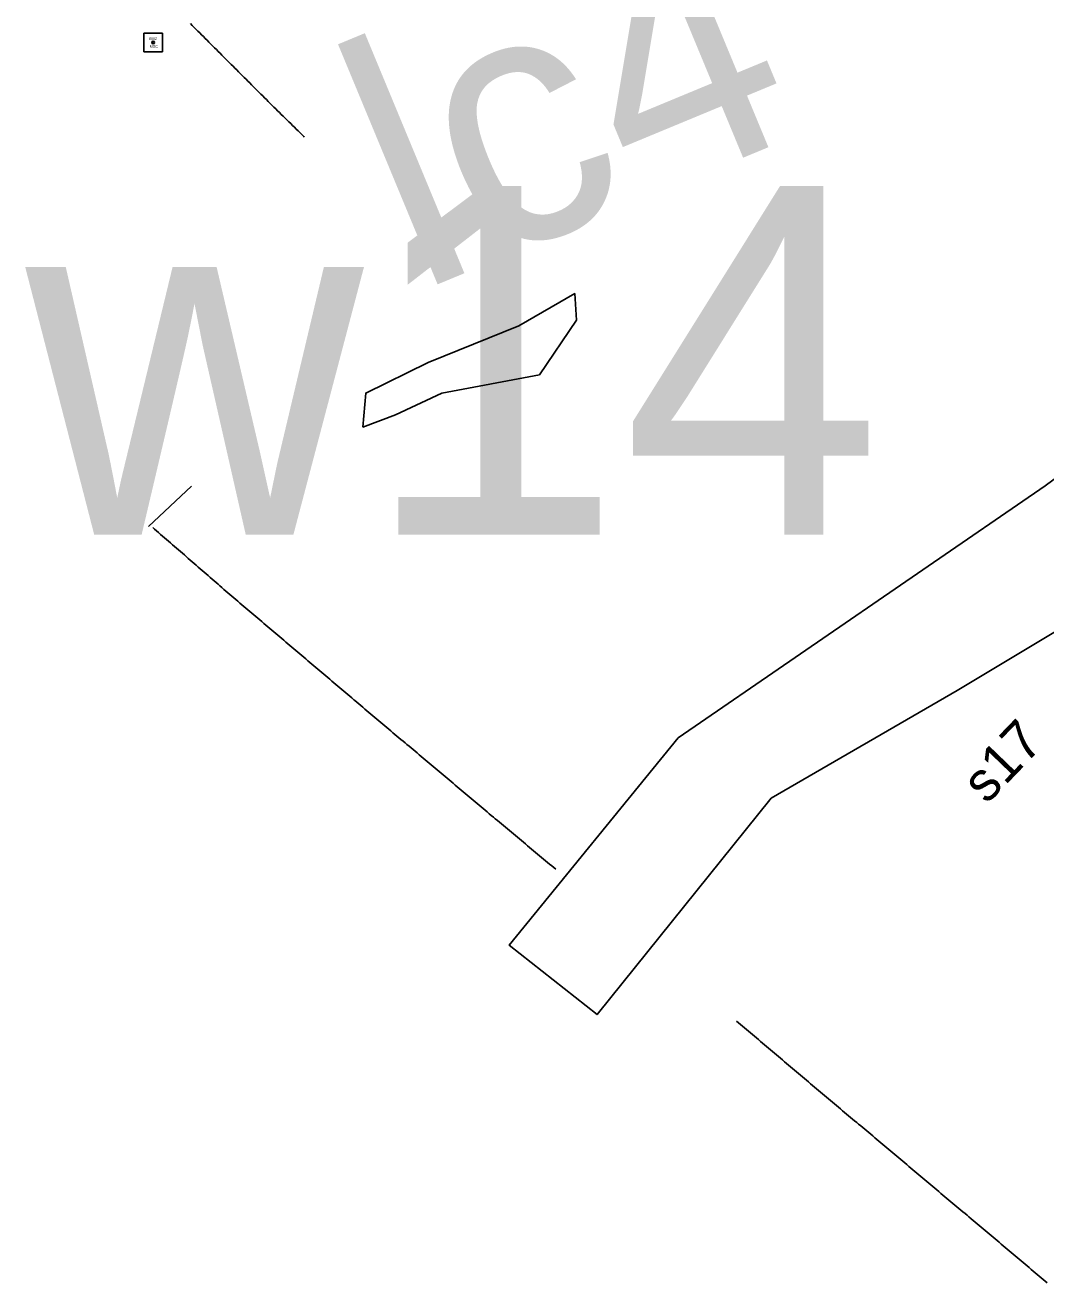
# Model space of a CAD drawing. Extents: x 205929 to 2357175, y -1785700 to 846739.
# Drawn here: x 2015000.6 to 2015389.7, y 820120.8 to 820600.5 of the extents above; entities that cross this region are included whole.
import ezdxf

# ---------------------------------------------------------------- set-up
doc = ezdxf.new("R2010")
doc.units = 0
for name, color, linetype in [('Default', 7, 'Continuous'), ('RD_EV_JTrib', 7, 'Continuous'), ('RD_EV_JW', 7, 'Continuous'), ('RD_EV_TX', 7, 'Continuous'), ('RD_HC_Survey', 7, 'Continuous'), ('RD_HC_txCode', 7, 'Continuous'), ('RD_Sketch1', 7, 'Continuous'), ('RD_SMD_Locator', 7, 'Continuous')]:
    doc.layers.add(name, color=color, linetype=linetype)

# ---------------------------------------------------------------- blocks, each defined once
blk = doc.blocks.new('POL00035')
at = {"layer": 'Default'}
blk.add_lwpolyline([(-11.11, -6.11), (-10.83, -2.82), (-4.79, 0.15), (4, 3.68), (9.41, 6.81), (9.59, 4.24), (5.99, -1.07), (-3.47, -2.84), (-7.94, -4.92)], close=True, dxfattribs=at)
blk = doc.blocks.new('POL0004A')
at = {"layer": 'Default'}
blk.add_lwpolyline([(60.33, 13.59), (59.28, 8.76), (45.95, 7.51), (36.02, 6.26), (27.95, 7.47), (13.76, 1.34), (-7.33, -11.33), (-25.33, -21.78), (-42.2, -42.73), (-50.71, -36.02), (-34.36, -15.93), (1.19, 8.51), (18.3, 21.11), (10.42, 34.97), (6.36, 42.61), (11.85, 51.93), (21.89, 20.87), (27.16, 12.26), (33.82, 12.71), (47.53, 14.82)], close=True, dxfattribs=at)

msp = doc.modelspace()

# ---------------------------------------------------------------- linework, layer by layer
at = {"layer": 'RD_HC_Survey'}
msp.add_lwpolyline([(2015052.92, 820597.45), (2015045.85, 820597.45), (2015045.85, 820590.38), (2015052.92, 820590.38)], close=True, dxfattribs=at)
msp.add_circle((2015049.38, 820593.91), 0.5, dxfattribs=at)
at = {"layer": 'RD_Sketch1'}
for points in [[(2015063.58, 820601.1), (2015064.29, 820600.39), (2015065, 820599.68), (2015065.7, 820598.98), (2015066.41, 820598.27), (2015067.11, 820597.56), (2015067.82, 820596.85), (2015068.53, 820596.14), (2015069.23, 820595.44), (2015069.94, 820594.73), (2015070.65, 820594.02), (2015071.36, 820593.32), (2015072.06, 820592.61), (2015072.77, 820591.9), (2015073.48, 820591.19), (2015074.18, 820590.49), (2015074.89, 820589.78), (2015075.6, 820589.07), (2015076.3, 820588.36), (2015077.01, 820587.66), (2015077.72, 820586.95), (2015078.42, 820586.24), (2015079.13, 820585.54), (2015079.84, 820584.83), (2015080.54, 820584.12), (2015081.25, 820583.41), (2015081.96, 820582.71), (2015082.67, 820582), (2015083.37, 820581.29), (2015084.08, 820580.58), (2015084.79, 820579.88), (2015085.49, 820579.17), (2015086.2, 820578.46), (2015086.91, 820577.76), (2015087.61, 820577.05), (2015088.32, 820576.34), (2015089.03, 820575.63), (2015089.73, 820574.93), (2015090.44, 820574.22), (2015091.15, 820573.51), (2015091.86, 820572.8), (2015092.56, 820572.1), (2015093.27, 820571.39), (2015093.98, 820570.68), (2015094.68, 820569.98), (2015095.39, 820569.27), (2015096.11, 820568.57), (2015096.82, 820567.87), (2015097.53, 820567.17), (2015098.24, 820566.46), (2015098.96, 820565.76), (2015099.67, 820565.06), (2015100.38, 820564.36), (2015101.09, 820563.66), (2015101.81, 820562.96), (2015102.52, 820562.25), (2015103.23, 820561.55), (2015103.94, 820560.85), (2015104.66, 820560.15), (2015105.37, 820559.45), (2015106.08, 820558.75), (2015106.79, 820558.05), (2015107, 820557.84)], [(2015063.95, 820424.68), (2015047.61, 820409.24)], [(2015049.19, 820408.91), (2015049.95, 820408.25), (2015050.7, 820407.6), (2015051.46, 820406.94), (2015052.21, 820406.29), (2015052.97, 820405.63), (2015053.72, 820404.97), (2015054.48, 820404.32), (2015055.23, 820403.66), (2015055.99, 820403.01), (2015056.74, 820402.35), (2015057.5, 820401.7), (2015058.25, 820401.04), (2015059.01, 820400.39), (2015059.76, 820399.73), (2015060.52, 820399.07), (2015061.27, 820398.42), (2015062.03, 820397.76), (2015062.78, 820397.11), (2015063.54, 820396.45), (2015064.29, 820395.8), (2015065.05, 820395.14), (2015065.8, 820394.49), (2015066.56, 820393.83), (2015067.31, 820393.18), (2015068.07, 820392.52), (2015068.82, 820391.86), (2015069.58, 820391.21), (2015070.33, 820390.55), (2015071.09, 820389.9), (2015071.84, 820389.24), (2015072.6, 820388.59), (2015073.35, 820387.93), (2015074.11, 820387.28), (2015074.86, 820386.62), (2015075.61, 820385.96), (2015076.37, 820385.31), (2015077.12, 820384.65), (2015077.88, 820384), (2015078.64, 820383.35), (2015079.4, 820382.7), (2015080.17, 820382.06), (2015080.93, 820381.41), (2015081.69, 820380.76), (2015082.45, 820380.11), (2015083.22, 820379.47), (2015083.98, 820378.82), (2015084.74, 820378.17), (2015085.5, 820377.53), (2015086.26, 820376.88), (2015087.03, 820376.23), (2015087.79, 820375.59), (2015088.55, 820374.94), (2015089.31, 820374.29), (2015090.07, 820373.64), (2015090.84, 820373), (2015091.6, 820372.35), (2015092.36, 820371.7), (2015093.12, 820371.06), (2015093.89, 820370.41), (2015094.65, 820369.76), (2015095.41, 820369.11), (2015096.17, 820368.47), (2015096.93, 820367.82), (2015097.7, 820367.17), (2015097.7, 820367.17), (2015098.46, 820366.53), (2015099.22, 820365.88), (2015099.98, 820365.23), (2015100.75, 820364.58), (2015101.51, 820363.94), (2015102.27, 820363.29), (2015103.03, 820362.64), (2015103.79, 820362), (2015104.56, 820361.35), (2015105.32, 820360.7), (2015106.08, 820360.05), (2015106.84, 820359.41), (2015107.61, 820358.76), (2015108.37, 820358.11), (2015109.13, 820357.47), (2015109.89, 820356.82), (2015110.65, 820356.17), (2015111.42, 820355.52), (2015112.18, 820354.88), (2015112.94, 820354.23), (2015113.7, 820353.58), (2015114.46, 820352.94), (2015115.23, 820352.29), (2015115.99, 820351.64), (2015116.75, 820351), (2015117.51, 820350.35), (2015118.28, 820349.7), (2015119.04, 820349.05), (2015119.8, 820348.41), (2015120.56, 820347.76), (2015121.32, 820347.11), (2015122.09, 820346.47), (2015122.85, 820345.82), (2015123.61, 820345.17), (2015124.37, 820344.53), (2015125.13, 820343.88), (2015125.9, 820343.23), (2015126.29, 820342.9), (2015127.06, 820342.25), (2015127.82, 820341.61), (2015128.59, 820340.96), (2015129.35, 820340.32), (2015130.11, 820339.67), (2015130.88, 820339.03), (2015131.64, 820338.38), (2015132.41, 820337.74), (2015133.17, 820337.09), (2015133.94, 820336.45), (2015134.7, 820335.8), (2015135.46, 820335.16), (2015136.23, 820334.52), (2015136.99, 820333.87), (2015137.76, 820333.23), (2015138.52, 820332.58), (2015139.29, 820331.94), (2015140.05, 820331.29), (2015140.81, 820330.65), (2015141.58, 820330), (2015142.34, 820329.36), (2015143.11, 820328.71), (2015143.87, 820328.07), (2015144.64, 820327.42), (2015145.4, 820326.78), (2015146.16, 820326.13), (2015146.93, 820325.49), (2015147.69, 820324.84), (2015148.46, 820324.2), (2015149.22, 820323.55), (2015149.99, 820322.91), (2015150.75, 820322.26), (2015151.51, 820321.62), (2015152.28, 820320.97), (2015153.04, 820320.33), (2015153.81, 820319.69), (2015154.58, 820319.05), (2015155.34, 820318.4), (2015156.11, 820317.76), (2015156.87, 820317.12), (2015157.64, 820316.47), (2015158.4, 820315.83), (2015159.17, 820315.19), (2015159.94, 820314.54), (2015160.7, 820313.9), (2015161.47, 820313.26), (2015162.23, 820312.62), (2015163, 820311.97), (2015163.76, 820311.33), (2015164.53, 820310.69), (2015165.3, 820310.04), (2015166.06, 820309.4), (2015166.83, 820308.76), (2015167.59, 820308.11), (2015168.36, 820307.47), (2015169.12, 820306.83), (2015169.89, 820306.18), (2015170.66, 820305.54), (2015171.42, 820304.9), (2015172.19, 820304.26), (2015172.95, 820303.61), (2015173.72, 820302.97), (2015174.48, 820302.33), (2015175.25, 820301.68), (2015175.25, 820301.68), (2015176.02, 820301.04), (2015176.78, 820300.4), (2015177.55, 820299.75), (2015178.31, 820299.11), (2015179.08, 820298.47), (2015179.84, 820297.83), (2015180.61, 820297.18), (2015181.38, 820296.54), (2015182.14, 820295.9), (2015182.91, 820295.25), (2015183.67, 820294.61), (2015184.44, 820293.97), (2015185.2, 820293.32), (2015185.97, 820292.68), (2015186.74, 820292.04), (2015187.5, 820291.4), (2015188.27, 820290.76), (2015189.04, 820290.12), (2015189.81, 820289.48), (2015190.57, 820288.83), (2015191.34, 820288.19), (2015192.11, 820287.55), (2015192.88, 820286.91), (2015193.64, 820286.27), (2015194.41, 820285.63), (2015195.18, 820284.99), (2015195.95, 820284.35), (2015196.71, 820283.71), (2015197.48, 820283.06), (2015198.25, 820282.42), (2015199.02, 820281.78), (2015199.78, 820281.14), (2015200.55, 820280.5), (2015201.32, 820279.86), (2015202.09, 820279.22), (2015202.85, 820278.58), (2015202.92, 820278.53)], [(2015271.76, 820220.66), (2015272.52, 820220.02), (2015273.29, 820219.37), (2015274.05, 820218.72), (2015274.81, 820218.08), (2015275.58, 820217.43), (2015276.34, 820216.79), (2015277.1, 820216.14), (2015277.87, 820215.49), (2015278.63, 820214.85), (2015279.39, 820214.2), (2015280.16, 820213.56), (2015280.92, 820212.91), (2015281.68, 820212.27), (2015282.45, 820211.62), (2015283.21, 820210.97), (2015283.97, 820210.33), (2015284.74, 820209.68), (2015285.5, 820209.04), (2015286.26, 820208.39), (2015287.03, 820207.74), (2015287.79, 820207.1), (2015288.55, 820206.45), (2015289.32, 820205.81), (2015290.08, 820205.16), (2015290.84, 820204.51), (2015291.61, 820203.87), (2015292.37, 820203.22), (2015293.13, 820202.58), (2015293.9, 820201.93), (2015294.66, 820201.29), (2015295.42, 820200.64), (2015296.19, 820199.99), (2015296.95, 820199.35), (2015297.71, 820198.7), (2015298.48, 820198.06), (2015299.24, 820197.41), (2015300, 820196.76), (2015300.77, 820196.12), (2015301.53, 820195.47), (2015302.3, 820194.83), (2015303.06, 820194.19), (2015303.83, 820193.54), (2015304.59, 820192.9), (2015305.36, 820192.26), (2015306.12, 820191.61), (2015306.89, 820190.97), (2015307.66, 820190.33), (2015308.42, 820189.68), (2015309.19, 820189.04), (2015309.95, 820188.4), (2015310.72, 820187.75), (2015311.48, 820187.11), (2015312.25, 820186.47), (2015313.01, 820185.82), (2015313.78, 820185.18), (2015314.54, 820184.54), (2015315.31, 820183.89), (2015316.08, 820183.25), (2015316.84, 820182.61), (2015317.61, 820181.96), (2015318.37, 820181.32), (2015319.14, 820180.68), (2015319.9, 820180.03), (2015320.67, 820179.39), (2015320.67, 820179.39), (2015321.43, 820178.75), (2015322.2, 820178.1), (2015322.96, 820177.46), (2015323.73, 820176.82), (2015324.5, 820176.17), (2015325.26, 820175.53), (2015326.03, 820174.89), (2015326.79, 820174.24), (2015327.56, 820173.6), (2015328.32, 820172.96), (2015329.09, 820172.31), (2015329.85, 820171.67), (2015330.62, 820171.03), (2015331.38, 820170.38), (2015332.15, 820169.74), (2015332.92, 820169.1), (2015333.68, 820168.45), (2015334.45, 820167.81), (2015335.21, 820167.17), (2015335.97, 820166.52), (2015336.74, 820165.88), (2015337.5, 820165.23), (2015338.27, 820164.59), (2015339.03, 820163.95), (2015339.8, 820163.3), (2015340.56, 820162.66), (2015341.33, 820162.01), (2015342.09, 820161.37), (2015342.86, 820160.73), (2015343.62, 820160.08), (2015344.39, 820159.44), (2015345.15, 820158.8), (2015345.92, 820158.15), (2015346.68, 820157.51), (2015347.45, 820156.86), (2015348.21, 820156.22), (2015348.97, 820155.58), (2015349.74, 820154.93), (2015350.5, 820154.29), (2015351.27, 820153.64), (2015352.03, 820153), (2015352.8, 820152.36), (2015353.56, 820151.71), (2015354.33, 820151.07), (2015355.09, 820150.43), (2015355.86, 820149.78), (2015356.62, 820149.14), (2015357.39, 820148.49), (2015358.15, 820147.85), (2015358.92, 820147.21), (2015359.68, 820146.56), (2015360.44, 820145.92), (2015361.21, 820145.27), (2015361.97, 820144.63), (2015362.74, 820143.99), (2015363.5, 820143.34), (2015364.27, 820142.7), (2015365.03, 820142.05), (2015365.8, 820141.41), (2015366.56, 820140.77), (2015367.33, 820140.12), (2015368.09, 820139.48), (2015368.86, 820138.83), (2015369.62, 820138.19), (2015369.62, 820138.19), (2015370.38, 820137.55), (2015371.15, 820136.9), (2015371.91, 820136.26), (2015372.68, 820135.61), (2015373.44, 820134.97), (2015374.21, 820134.33), (2015374.97, 820133.68), (2015375.74, 820133.04), (2015376.5, 820132.39), (2015377.27, 820131.75), (2015378.03, 820131.11), (2015378.79, 820130.46), (2015379.56, 820129.82), (2015380.32, 820129.17), (2015381.09, 820128.53), (2015381.85, 820127.89), (2015382.62, 820127.24), (2015383.38, 820126.6), (2015384.15, 820125.95), (2015384.91, 820125.31), (2015385.68, 820124.67), (2015386.44, 820124.02), (2015387.2, 820123.38), (2015387.97, 820122.73), (2015388.73, 820122.09), (2015389.5, 820121.45), (2015390.26, 820120.8)]]:
    msp.add_lwpolyline(points, dxfattribs=at)
at = {"layer": 'RD_SMD_Locator'}
msp.add_circle((2015049.38, 820593.91), 0.001, dxfattribs=at)

# ---------------------------------------------------------------- block references
at = {"layer": 'RD_EV_JTrib', "xscale": 3.937007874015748, "yscale": 3.937007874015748}
msp.add_blockref('POL0004A', (2015384.79, 820391.36), dxfattribs=at)
at = {"layer": 'RD_EV_JW', "xscale": 3.937007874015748, "yscale": 3.937007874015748}
msp.add_blockref('POL00035', (2015173.06, 820471.29), dxfattribs=at)

# ---------------------------------------------------------------- texts
at = {"layer": 'RD_EV_TX'}
for s, height, rotation, p in [('lc4', 94.115, 22.5227, (2015150, 820498.4)), ('s17', 15, 46.0699, (2015367.19, 820303.09))]:
    msp.add_text(s, height=height, rotation=rotation, dxfattribs=at).set_placement(p)
msp.add_text('w14', height=133.064, dxfattribs=at).set_placement((2015000.84, 820406.14))
at = {"layer": 'RD_HC_txCode'}
for s, p in [('8552', (2015047.75, 820594.91)), ('MSC', (2015048.07, 820591.91))]:
    msp.add_text(s, height=1, dxfattribs=at).set_placement(p)

doc.saveas('drawing.dxf')
